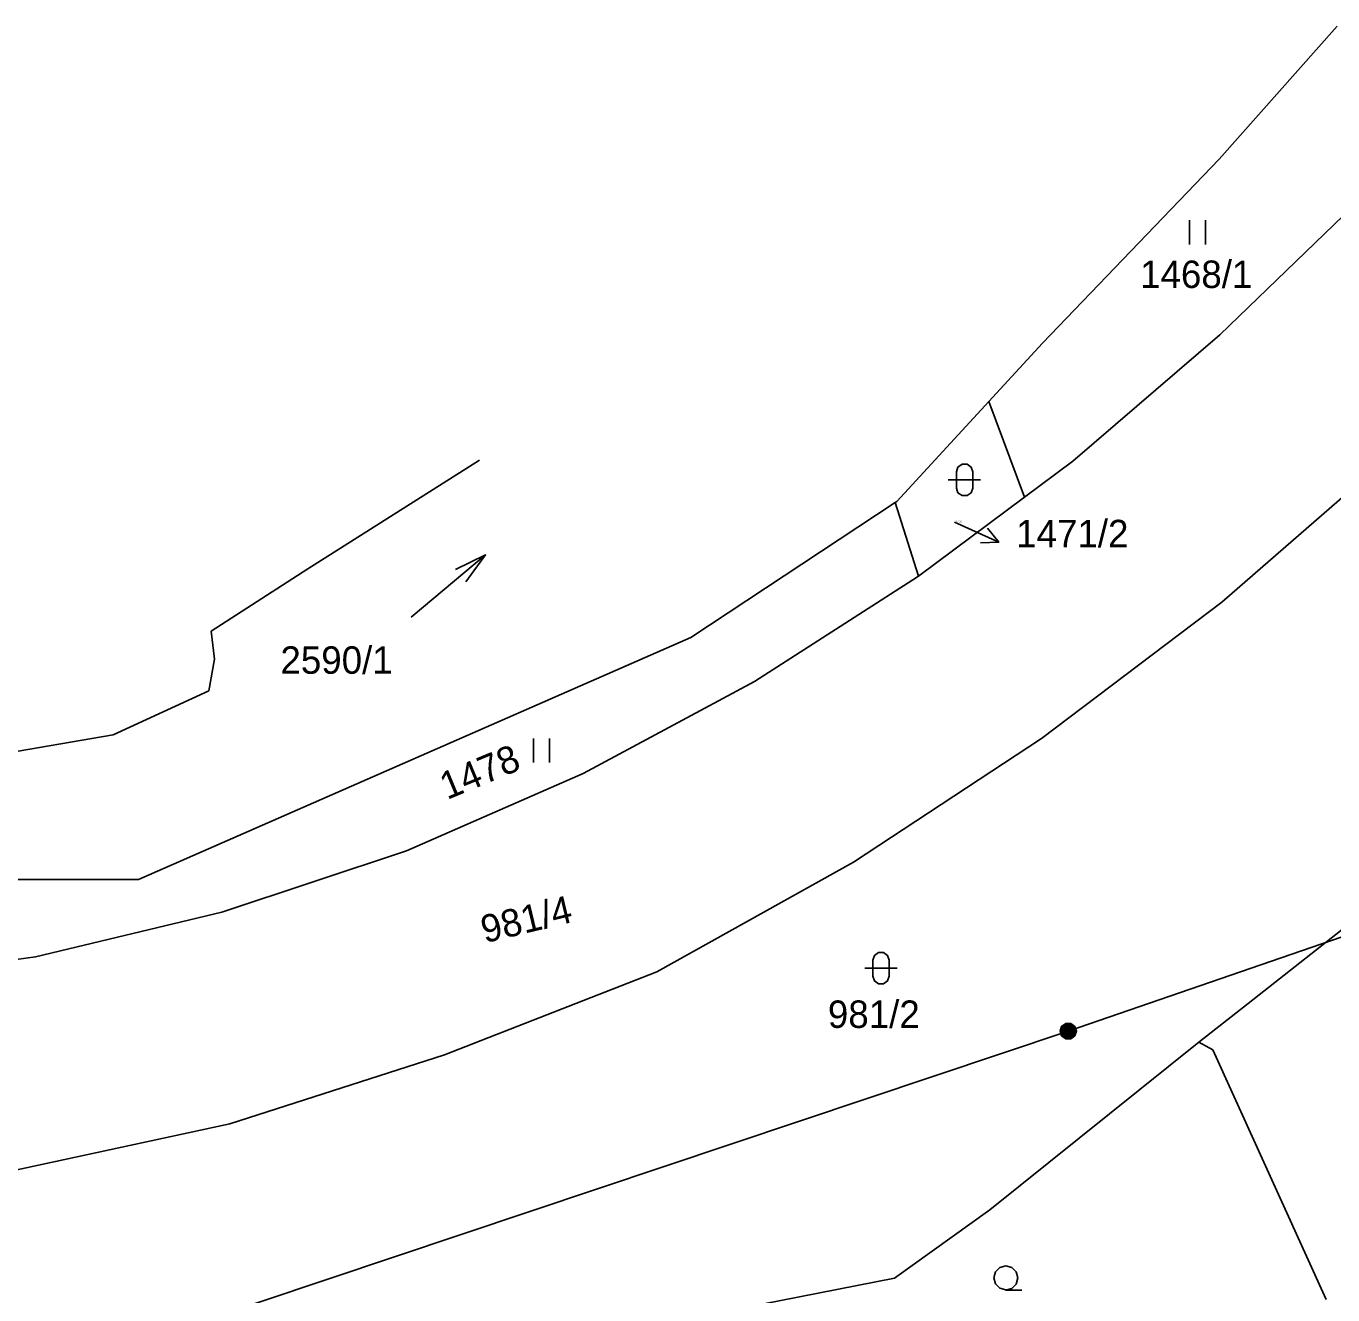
# Model space of a CAD drawing. Extents: x -806774 to -803680, y -1151731 to -1150053.
# Drawn here: x -805196.8 to -805115.9, y -1150574.5 to -1150495.9 of the extents above; entities that cross this region are included whole.
import ezdxf

# ---------------------------------------------------------------- set-up
doc = ezdxf.new("R2010")
doc.units = 0
for name, color, linetype in [('1', 7, 'Continuous'), ('2', 7, 'Continuous'), ('3', 7, 'Continuous'), ('6', 7, 'Continuous'), ('7', 7, 'Continuous')]:
    doc.layers.add(name, color=color, linetype=linetype)

msp = doc.modelspace()

# ---------------------------------------------------------------- linework, layer by layer
at = {"layer": '1'}
for p, q in [((-805122.96, -1150504.14), (-805115.65, -1150495.91)), ((-805122.96, -1150504.14), (-805133.9, -1150515.55)), ((-805122.93, -1150515.03), (-805113.96, -1150506.36)), ((-805132.03, -1150522.85), (-805122.93, -1150515.03)), ((-805133.9, -1150515.55), (-805137.23, -1150519.16)), ((-805137.23, -1150519.16), (-805142.93, -1150525.35)), ((-805137.23, -1150519.16), (-805135.02, -1150525.08)), ((-805168.76, -1150522.8), (-805179.41, -1150529.53)), ((-805135.02, -1150525.08), (-805132.03, -1150522.85)), ((-805122.81, -1150531.59), (-805112.27, -1150522.42)), ((-805143.03, -1150525.41), (-805155.69, -1150533.78)), ((-805142.93, -1150525.35), (-805143.03, -1150525.41)), ((-805143.03, -1150525.41), (-805141.58, -1150529.98)), ((-805141.58, -1150529.98), (-805135.02, -1150525.08)), ((-805185.38, -1150533.39), (-805179.41, -1150529.53)), ((-805151.75, -1150536.51), (-805141.65, -1150530.03)), ((-805141.65, -1150530.03), (-805141.58, -1150529.98)), ((-805133.96, -1150540.03), (-805122.81, -1150531.59)), ((-805185.38, -1150533.39), (-805185.18, -1150535.11)), ((-805155.69, -1150533.78), (-805189.88, -1150548.76)), ((-805185.18, -1150535.11), (-805185.54, -1150537.09)), ((-805162.36, -1150542.2), (-805151.75, -1150536.51)), ((-805191.45, -1150539.81), (-805185.54, -1150537.09)), ((-805201.89, -1150541.59), (-805191.45, -1150539.81)), ((-805145.61, -1150547.7), (-805133.96, -1150540.03)), ((-805121.16, -1150556.44), (-805102.15, -1150541.44)), ((-805173.3, -1150546.99), (-805162.36, -1150542.2)), ((-805173.3, -1150546.99), (-805184.73, -1150550.79)), ((-805157.79, -1150554.48), (-805145.61, -1150547.7)), ((-805200.33, -1150548.77), (-805189.88, -1150548.76)), ((-805184.73, -1150550.79), (-805196.27, -1150553.55)), ((-805196.27, -1150553.55), (-805208.08, -1150555.25)), ((-805170.94, -1150559.63), (-805157.79, -1150554.48)), ((-805124.23, -1150558.85), (-805121.16, -1150556.44)), ((-805137.16, -1150569.23), (-805124.23, -1150558.85)), ((-805124.23, -1150558.85), (-805123.35, -1150559.31)), ((-805123.35, -1150559.31), (-805116.35, -1150574.79)), ((-805184.24, -1150563.91), (-805170.94, -1150559.63)), ((-805197.9, -1150566.86), (-805184.24, -1150563.91)), ((-805143.08, -1150573.46), (-805137.16, -1150569.23)), ((-805156, -1150576), (-805143.08, -1150573.46))]:
    msp.add_line(p, q, dxfattribs=at)
at = {"layer": '3'}
for p, q in [((-805124.81, -1150507.93), (-805124.81, -1150509.43)), ((-805123.81, -1150509.43), (-805123.81, -1150507.93)), ((-805172.998, -1150532.516), (-805168.397, -1150528.665)), ((-805165.43, -1150540.03), (-805165.43, -1150541.53)), ((-805164.43, -1150541.53), (-805164.43, -1150540.03))]:
    msp.add_line(p, q, dxfattribs=at)
for points in [[(-805139.24, -1150523.52), (-805139.14, -1150523.23), (-805138.89, -1150523.05), (-805138.58, -1150523.05), (-805138.33, -1150523.23), (-805138.23, -1150523.52), (-805138.23, -1150524.52), (-805138.33, -1150524.81), (-805138.58, -1150524.99), (-805138.89, -1150524.99), (-805139.14, -1150524.81), (-805139.24, -1150524.52)], [(-805144.41, -1150553.76), (-805144.31, -1150553.47), (-805144.06, -1150553.29), (-805143.75, -1150553.29), (-805143.5, -1150553.47), (-805143.4, -1150553.76), (-805143.4, -1150554.76), (-805143.5, -1150555.05), (-805143.75, -1150555.23), (-805144.06, -1150555.23), (-805144.31, -1150555.05), (-805144.41, -1150554.76)]]:
    msp.add_lwpolyline(points, close=True, dxfattribs=at)
for points in [[(-805139.74, -1150524.02), (-805138.47, -1150524.02), (-805137.74, -1150524.02)], [(-805170.252, -1150529.565), (-805168.397, -1150528.665), (-805169.61, -1150530.332)], [(-805144.91, -1150554.26), (-805143.64, -1150554.26), (-805142.91, -1150554.26)], [(-805136.17, -1150574.18), (-805136.55, -1150574.08), (-805136.82, -1150573.81), (-805136.92, -1150573.44), (-805136.82, -1150573.07), (-805136.55, -1150572.8), (-805136.18, -1150572.7), (-805135.81, -1150572.8), (-805135.54, -1150573.07), (-805135.44, -1150573.45), (-805135.54, -1150573.83), (-805135.81, -1150574.1), (-805136.19, -1150574.2), (-805135.19, -1150574.2)]]:
    msp.add_lwpolyline(points, dxfattribs=at)
at = {"layer": '6'}
for p in [(-805055.64, -1150531.75), (-805267.37, -1150603.37)]:
    msp.add_line(p, (-805132.32, -1150558.17), dxfattribs=at)
msp.add_lwpolyline([(-805132.47, -1150557.69), (-805132.16, -1150557.69), (-805131.91, -1150557.87), (-805131.81, -1150558.16), (-805131.91, -1150558.45), (-805132.16, -1150558.63), (-805132.47, -1150558.63), (-805132.72, -1150558.45), (-805132.82, -1150558.16), (-805132.72, -1150557.87), (-805132.47, -1150557.69), (-805132.44, -1150557.73), (-805132.2, -1150557.73), (-805132.04, -1150557.81), (-805132.6, -1150557.81), (-805132.68, -1150557.89), (-805131.96, -1150557.89), (-805131.96, -1150557.97), (-805132.68, -1150557.97), (-805132.72, -1150558.05), (-805131.92, -1150558.05), (-805131.88, -1150558.13), (-805132.76, -1150558.13), (-805132.76, -1150558.21), (-805131.88, -1150558.21), (-805131.91, -1150558.29), (-805132.72, -1150558.29), (-805132.71, -1150558.37), (-805131.9, -1150558.37), (-805131.95, -1150558.45), (-805132.67, -1150558.45), (-805132.59, -1150558.53), (-805132.03, -1150558.53), (-805132.14, -1150558.61), (-805132.48, -1150558.61)], dxfattribs=at)
at = {"layer": '7'}
msp.add_line((-805136.619, -1150527.881), (-805139.35, -1150526.64), dxfattribs=at)
msp.add_lwpolyline([(-805137.322, -1150527.012), (-805136.619, -1150527.881), (-805137.736, -1150527.922)], dxfattribs=at)

# ---------------------------------------------------------------- texts
at = {"layer": '2'}
for s, height, p in [('1468/1', 1.7, (-805127.863, -1150512.13)), ('1471/2', 0.1, (-805139.327, -1150526.64)), ('2590/1', 1.7, (-805181.098, -1150536.025)), ('981/2', 1.7, (-805147.196, -1150557.96))]:
    msp.add_text(s, height=height, dxfattribs=at).set_placement(p)
for s, rotation, p in [('1478', 22.51724, (-805170.776, -1150543.847)), ('981/4', 13.5218, (-805168.446, -1150552.716))]:
    msp.add_text(s, height=1.7, rotation=rotation, dxfattribs=at).set_placement(p)
at = {"layer": '7'}
msp.add_text('1471/2', height=1.7, dxfattribs=at).set_placement((-805135.537, -1150528.19))

doc.saveas('drawing.dxf')
